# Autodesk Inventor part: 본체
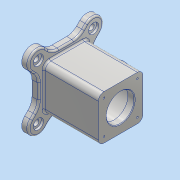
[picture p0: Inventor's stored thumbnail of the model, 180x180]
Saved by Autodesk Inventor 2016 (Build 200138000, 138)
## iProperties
Created: 2019-11
Part Number: 본체
Material: 알루미늄 6061
Document SubType Name: Modeling
Designer: user
Density: 2.7 g/cm^3
Appearance: 알루미늄 - 평지
Mass: 1076.28 g
Surface Area: 879.96 cm^2
Volume: 398.62 cm^3
Author: user
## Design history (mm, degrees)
sketch "스케치1"
  geometry: L1 (49, 49)-(-49, 49); L2 (-49, 49)-(-49, -49); L3 (-49, -49)-(49, -49); L4 (49, -49)-(49, 49); L5 (49, 49)-(-49, -49); L6 (-49, 49)-(49, -49); L7 (-49.497, 49.497)-(49.497, -49.497); L8 (-62.225, 36.77)-(36.77, -62.225); L9 (62.225, -36.77)-(-36.77, 62.225); L10 (-49.497, -49.497)-(49.497, 49.497); L11 (-36.77, -62.225)-(62.225, 36.77); L12 (36.77, 62.225)-(-62.225, -36.77); A1 r 18 centre (-49.497, 49.497) between (-36.77, 62.225) and (-62.225, 36.77); A2 r 18 centre (49.497, -49.497) between (36.77, -62.225) and (62.225, -36.77); A3 r 18 centre (-49.497, -49.497) between (-62.225, -36.77) and (-36.77, -62.225); A4 r 18 centre (49.497, 49.497) between (62.225, 36.77) and (36.77, 62.225); A5 r 70 centre (0, 0) between (49.497, -49.497) and (-49.497, -49.497); 1 further point
  constraints: 28 end point, 10 point on circle, 8 tangent, 5 centre point, 4 midpoint, 4 parallel, 2 point on line, 1 coincident, 1 horizontal, 1 perpendicular
  dimensions: "d0" = 98 distance of L3.end L2.end; "d1" = 98 distance of L2.end L1.end; "d2" = 36 diameter of A2; "d3" = 36 diameter of A4; "d4" = 70 radius of A5
extrude "돌출1" new body sketch "스케치1" distance "d5" = 12; taper "d6" = 0 deg
sketch "스케치2"
  geometry: L1 (-40, 40)-(40, 40); L2 (40, 40)-(40, -40); L3 (40, -40)-(-40, -40); L4 (-40, -40)-(-40, 40); L5 (-40, 40)-(40, -40); L6 (40, 40)-(-40, -40); 1 further point
  constraints: 12 end point, 2 midpoint, 2 parallel, 1 horizontal, 1 perpendicular
  dimensions: "d7" = 80 distance of L2.end L3.end; "d8" = 80 distance of L1.end L2.end
extrude "돌출2" join sketch "스케치2" distance "d9" = 98; taper "d10" = 0 deg
sketch "스케치3"
  geometry: L1 (-30, 30)-(30, 30); L2 (30, 30)-(30, -30); L3 (30, -30)-(-30, -30); L4 (-30, -30)-(-30, 30); L5 (-30, 30)-(30, -30); L6 (30, 30)-(-30, -30); 5 further points
  constraints: 12 end point, 4 coincident, 2 midpoint, 2 parallel, 1 horizontal, 1 perpendicular
  dimensions: "d11" = 60 distance of L2.end L3.end; "d12" = 60 distance of L1.end L2.end
hole "구멍1" sketch "스케치3" at (-30, 30), (-30, -30), (30, -30), (30, 30) diameter "d13" = 3.242; stored, may be unused: countersink angle "d17" = 90 deg, drill point angle "d19" = 118 deg; dims "d14" = 8, "d15" = 4, "d16" = 2, "d18" = 10
node "작업 평면2"
  node "작업 평면1"
sketch "스케치5"
  geometry: A1 r 18 centre (-49.497, 49.497) between (-36.77, 62.225) and (-62.225, 36.77) reference; A2 r 18 centre (49.497, 49.497) between (62.225, 36.77) and (36.77, 62.225) reference; A3 r 18 centre (49.497, -49.497) between (36.77, -62.225) and (62.225, -36.77) reference; A4 r 18 centre (-49.497, -49.497) between (-62.225, -36.77) and (-36.77, -62.225) reference; 5 further points
  constraints: 4 coincident
hole "구멍3" sketch "스케치5" at (-49.497, 49.497), (49.497, 49.497), (49.497, -49.497), (-49.497, -49.497) diameter "d29" = 10; stored, may be unused: countersink angle "d33" = 90 deg, drill point angle "d35" = 118 deg; dims "d30" = 8, "d31" = 18, "d32" = 4, "d34" = 50
node "작업 평면3"
sketch "스케치8"
  geometry: L1 (-12, 67.497)-(-12, 36.77) reference; L2 (-12, -40)-(-110, -40) reference; C1 r 20 at (-61, 0); 2 further points
  constraints: 1 centre point
  dimensions: "d40" = 40 diameter of C1; "d41" = 49 distance from line of L1 C1.centre; "d42" = 40 distance from line of L2 C1.centre
extrude "돌출3" join sketch "스케치8" stored distance "d43" = 98; taper "d44" = 0 deg
sketch "스케치9"
  geometry: C1 r 25 at (0, 0); 1 further point
  constraints: 1 centre point, 1 coincident
  dimensions: "d45" = 50 diameter of C1
extrude "돌출4" cut sketch "스케치9" distance "d46" = 12; taper "d47" = 0 deg
sketch "스케치10"
  geometry: C1 r 35 at (0, 0); 1 further point
  constraints: 1 centre point, 1 coincident
  dimensions: "d48" = 70 diameter of C1
extrude "돌출5" cut sketch "스케치10" distance "d49" = 86; taper "d50" = 0 deg
sketch "스케치11"
  geometry: C1 r 25 at (0, 0); 1 further point
  constraints: 1 centre point, 1 coincident
  dimensions: "d51" = 50 diameter of C1
extrude "돌출6" cut sketch "스케치11" distance "d52" = 12; taper "d53" = 0 deg
sketch "스케치12"
  geometry: C1 r 20 at (0, 0) reference; 2 further points
  constraints: 1 coincident
hole "구멍4" sketch "스케치12" at (0, 0) diameter "d54" = 25; stored, may be unused: countersink angle "d58" = 90 deg, drill point angle "d60" = 118 deg; dims "d55" = 8, "d56" = 30, "d57" = 8, "d59" = 50
fillet "모깎기1" dims "d61" = 25
fillet "모깎기2" dims "d62" = 10
fillet "모깎기3" dims "d63" = 3
fillet "모깎기4" dims "d64" = 3
fillet "모깎기5" dims "d65" = 3
fillet "모깎기6" dims "d66" = 3
chamfer "모따기1" distance "d67" = 1; stored, may be unused: second distance "d68" = 2, angle "d69" = 45 deg
sketch "스케치13"
  geometry: L1 (0, 60)-(0, 0) reference; L2 (-98, 16.811)-(-98, 43.189) reference; 3 further points
  constraints: 1 horizontal alignment, 1 midpoint, 1 other
  dimensions: "d70" = 10 distance from line of L1 point (-10, 30)
feature "엠보싱1" sketch "스케치13" dims "d0" = 98, "d1" = 98, "d2" = 36, "d3" = 36, "d4" = 70, "d71" = 0.5, "d72" = 0
node "솔리드1"
mirror "대칭1"
other parameters: "d20" = 55, "d21" = -12, "d39" = 55
